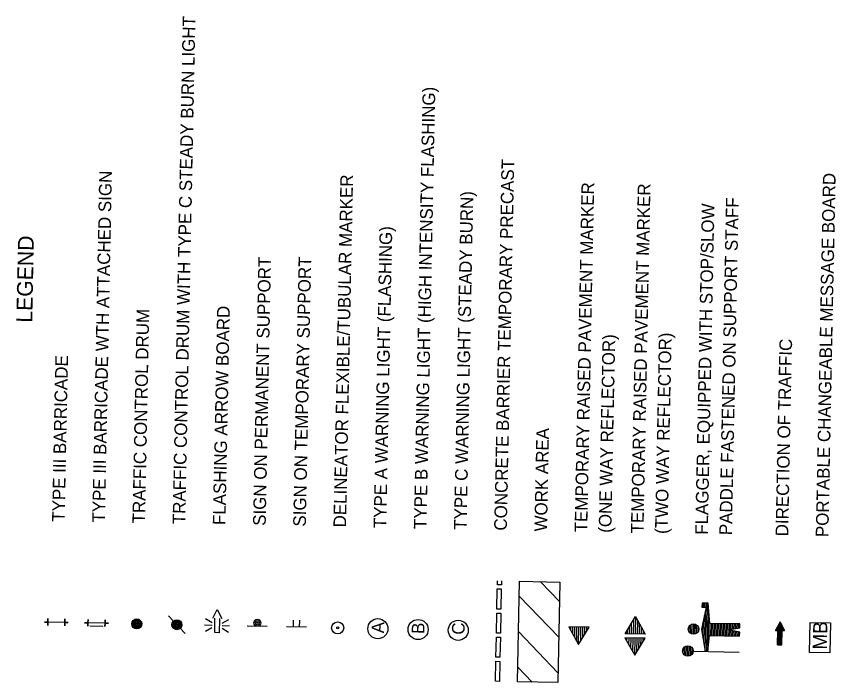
# Model space of a CAD drawing. Extents: x 327762 to 372792, y 127949 to 259367.
# Drawn here: x 327762 to 339988, y 174328 to 184269 of the extents above; entities that cross this region are included whole.
import ezdxf

# ---------------------------------------------------------------- set-up
doc = ezdxf.new("R2010")
doc.units = 0
for name, color, linetype in [('P_TC', 7, 'Continuous'), ('P_TC_BarrierConc', 7, 'Continuous'), ('P_TC_FlowArrow', 7, 'Continuous'), ('P_TC_Text', 7, 'Continuous')]:
    doc.layers.add(name, color=color, linetype=linetype)

msp = doc.modelspace()

# ---------------------------------------------------------------- linework, layer by layer
at = {"layer": 'P_TC'}
for p, q in [((335867, 175537), (335582, 175833)), ((335856, 175006), (335266, 175620)), ((338054, 175453), (337988, 175125)), ((337996, 175515), (337994, 175455)), ((337994, 175455), (338054, 175453)), ((338088, 175513), (337996, 175515)), ((338010, 175454), (338011, 175514)), ((338032, 175454), (338033, 175514)), ((338041, 174793), (338056, 175513)), ((338064, 174793), (338078, 175513)), ((338110, 175212), (338088, 175513)), ((330692, 175289), (330761, 175419)), ((330761, 175419), (330827, 175286)), ((338022, 174936), (338030, 175331)), ((338088, 174884), (338098, 175376)), ((328231, 175231), (328180, 175232)), ((328180, 175232), (328231, 175231)), ((328231, 175231), (328229, 175180)), ((328229, 175180), (328231, 175231)), ((328231, 175231), (328232, 175282)), ((328232, 175282), (328231, 175231)), ((328485, 175226), (328231, 175231)), ((328485, 175226), (328484, 175175)), ((328484, 175175), (328485, 175226)), ((328486, 175277), (328485, 175226)), ((328485, 175226), (328486, 175277)), ((328485, 175226), (328536, 175225)), ((328536, 175225), (328485, 175226)), ((328830, 175219), (328779, 175220)), ((328779, 175220), (328830, 175219)), ((328830, 175219), (328829, 175168)), ((328829, 175168), (328830, 175219)), ((328830, 175219), (328831, 175270)), ((328831, 175270), (328830, 175219)), ((329085, 175214), (328830, 175219)), ((329085, 175214), (329084, 175163)), ((329084, 175163), (329085, 175214)), ((329086, 175265), (329085, 175214)), ((329085, 175214), (329086, 175265)), ((329085, 175214), (329136, 175213)), ((329136, 175213), (329085, 175214)), ((330283, 175062), (330032, 175323)), ((330683, 175219), (330586, 175278)), ((330722, 175074), (330726, 175288)), ((330793, 175286), (330789, 175073)), ((330834, 175216), (330932, 175271)), ((331898, 175157), (331900, 175262)), ((331988, 175156), (331990, 175261)), ((336939, 175212), (336936, 175056)), ((336970, 175263), (336966, 175055)), ((337001, 175314), (336996, 175055)), ((337030, 175262), (337026, 175054)), ((337059, 175209), (337056, 175053)), ((337866, 175049), (337870, 175206)), ((338001, 175049), (338005, 175208)), ((338560, 175203), (338110, 175212)), ((338114, 175032), (338117, 175212)), ((338136, 175032), (338140, 175212)), ((338159, 175031), (338162, 175211)), ((338181, 175031), (338185, 175211)), ((338204, 175030), (338207, 175210)), ((338226, 175030), (338230, 175210)), ((338249, 175029), (338252, 175209)), ((338271, 175029), (338275, 175209)), ((338294, 175029), (338297, 175209)), ((338316, 175028), (338320, 175208)), ((338339, 175028), (338342, 175208)), ((338361, 175027), (338365, 175207)), ((338385, 175119), (338387, 175207)), ((338408, 175122), (338410, 175206)), ((338431, 175125), (338432, 175206)), ((338453, 175128), (338455, 175205)), ((338476, 175131), (338477, 175205)), ((338498, 175135), (338500, 175204)), ((338521, 175138), (338522, 175204)), ((338543, 175141), (338545, 175204)), ((338558, 175143), (338560, 175203)), ((329054, 175164), (328859, 175168)), ((330682, 175182), (330570, 175184)), ((330681, 175144), (330583, 175090)), ((330832, 175141), (330929, 175083)), ((330833, 175179), (330945, 175177)), ((331506, 175165), (331207, 175171)), ((332093, 175153), (331793, 175159)), ((335845, 174476), (335256, 175090)), ((336037, 175109), (336038, 175161)), ((336066, 175056), (336068, 175160)), ((336095, 175004), (336098, 175159)), ((336124, 174951), (336128, 175159)), ((336153, 174898), (336158, 175158)), ((336184, 174950), (336188, 175158)), ((336215, 175001), (336218, 175157)), ((336246, 175052), (336248, 175156)), ((336277, 175104), (336278, 175156)), ((336877, 175109), (336876, 175057)), ((336908, 175160), (336906, 175056)), ((337088, 175157), (337086, 175053)), ((337117, 175104), (337116, 175052)), ((337800, 175088), (337801, 175169)), ((337822, 175064), (337824, 175192)), ((337844, 175052), (337847, 175203)), ((337889, 175052), (337892, 175202)), ((337912, 175062), (337914, 175190)), ((337935, 175086), (337936, 175165)), ((337988, 175125), (338041, 174794)), ((338378, 175117), (338558, 175143)), ((338557, 175083), (338378, 175117)), ((338384, 175027), (338385, 175115)), ((338406, 175026), (338408, 175111)), ((338429, 175026), (338430, 175107)), ((338451, 175025), (338453, 175103)), ((338474, 175025), (338475, 175098)), ((338496, 175024), (338497, 175094)), ((338519, 175024), (338520, 175090)), ((338541, 175024), (338542, 175086)), ((338556, 175023), (338557, 175083)), ((330789, 175073), (330722, 175074)), ((336874, 174945), (336875, 174997)), ((336903, 174893), (336905, 174997)), ((336932, 174840), (336935, 174996)), ((336961, 174787), (336965, 174995)), ((336990, 174735), (336995, 174995)), ((337021, 174786), (337025, 174994)), ((337052, 174838), (337055, 174993)), ((337083, 174889), (337085, 174993)), ((337114, 174940), (337115, 174992)), ((338079, 174793), (338106, 175032)), ((338106, 175032), (338556, 175023)), ((337715, 174760), (337716, 174840)), ((337737, 174735), (337739, 174864)), ((337759, 174724), (337762, 174874)), ((337781, 174720), (337785, 174877)), ((337804, 174723), (337807, 174873)), ((337827, 174734), (337829, 174862)), ((337850, 174758), (337851, 174837)), ((337861, 174797), (338551, 174783)), ((335460, 174335), (335245, 174560))]:
    msp.add_line(p, q, dxfattribs=at)
for points in [[(335241, 174340), (335271, 175840), (335872, 175827), (335842, 174328)], [(337146, 175052), (336846, 175058), (337001, 175314)], [(339601, 174777), (339610, 175227), (339910, 175221), (339901, 174771)], [(336308, 175155), (336008, 175161), (336153, 174898)], [(337145, 174992), (336845, 174998), (336990, 174735)]]:
    msp.add_lwpolyline(points, close=True, dxfattribs=at)
for centre, radius in [((329558, 175204), 75), ((329558, 175204), 60), ((329558, 175204), 45), ((329558, 175204), 30), ((329558, 175204), 15), ((329558, 175204), 7.5), ((330158, 175192), 75), ((330158, 175192), 60), ((330158, 175192), 45), ((330158, 175192), 30), ((330158, 175192), 15), ((331358, 175221), 52.5), ((331358, 175221), 30), ((331358, 175221), 7.5), ((332557, 175144), 90), ((333157, 175132), 150), ((333757, 175120), 150), ((334357, 175108), 150), ((337868, 175127), 78.4), ((330158, 175192), 7.5), ((332557, 175144), 15), ((337783, 174799), 78.4)]:
    msp.add_circle(centre, radius, dxfattribs=at)
at = {"layer": 'P_TC_BarrierConc'}
msp.add_lwpolyline([(335002, 175845), (335001, 175785), (334941, 175786), (334942, 175846)], dxfattribs=at)
for points in [[(334933, 175426), (334939, 175726), (334999, 175725), (334993, 175425)], [(334926, 175066), (334932, 175366), (334992, 175365), (334986, 175065)], [(334919, 174706), (334925, 175006), (334985, 175005), (334979, 174705)], [(334912, 174347), (334918, 174646), (334978, 174645), (334972, 174345)]]:
    msp.add_lwpolyline(points, close=True, dxfattribs=at)
at = {"layer": 'P_TC_FlowArrow'}
for p, q in [((339160, 175236), (339091, 175106)), ((339148, 174891), (339154, 175225)), ((339160, 175236), (339226, 175103)), ((339161, 174891), (339168, 175221)), ((339091, 175106), (339226, 175103)), ((339098, 175106), (339098, 175119)), ((339111, 175106), (339112, 175145)), ((339121, 174891), (339125, 175105)), ((339125, 175106), (339126, 175172)), ((339134, 174891), (339140, 175198)), ((339175, 174890), (339181, 175195)), ((339188, 174890), (339192, 175104)), ((339192, 175104), (339194, 175169)), ((339206, 175104), (339207, 175142)), ((339219, 175104), (339220, 175116)), ((339121, 174891), (339188, 174890)), ((339154, 174891), (339154, 174891))]:
    msp.add_line(p, q, dxfattribs=at)

# ---------------------------------------------------------------- texts
at = {"layer": 'P_TC'}
for s, height, p in [('A', 189, (333250, 175062)), ('B', 189, (333850, 175053)), ('C', 189, (334450, 175041)), ('MB', 210, (339857, 174819))]:
    msp.add_text(s, height=height, rotation=88.8462, dxfattribs=at).set_placement(p)
at = {"layer": 'P_TC_Text'}
for s, height, p in [('TRAFFIC CONTROL DRUM WITH TYPE C STEADY BURN LIGHT', 189, (330282, 176690)), ('TYPE B WARNING LIGHT (HIGH INTENSITY FLASHING)', 189, (333882, 176618)), ('CONCRETE BARRIER TEMPORARY PRECAST', 189, (335081, 176594)), ('TYPE III BARRICADE WTH ATTACHED SIGN', 189, (329083, 176714)), ('DELINEATOR FLEXIBLE/TUBULAR MARKER', 189, (332682, 176642)), ('PORTABLE CHANGEABLE MESSAGE BOARD', 189, (339880, 176497)), ('TEMPORARY RAISED PAVEMENT MARKER', 189, (336281, 176569)), ('TEMPORARY RAISED PAVEMENT MARKER', 189, (337121, 176552)), ('TYPE C WARNING LIGHT (STEADY BURN)', 189, (334481, 176606)), ('FLAGGER, EQUIPPED WITH STOP/SLOW', 189, (338081, 176533)), ('PADDLE FASTENED ON SUPPORT STAFF', 189, (338441, 176526)), ('TYPE A WARNING LIGHT (FLASHING)', 189, (333282, 176630)), ('LEGEND', 236.4, (327998, 179697)), ('SIGN ON PERMANENT SUPPORT', 189, (331482, 176666)), ('SIGN ON TEMPORARY SUPPORT', 189, (332082, 176654)), ('TRAFFIC CONTROL DRUM', 189, (329682, 176702)), ('FLASHING ARROW BOARD', 189, (330882, 176678)), ('(ONE WAY REFLECTOR)', 189, (336641, 176562)), ('(TWO WAY REFLECTOR)', 189, (337481, 176545)), ('DIRECTION OF TRAFFIC', 189, (339280, 176509)), ('TYPE III BARRICADE', 189, (328483, 176726)), ('WORK AREA', 189, (335681, 176581))]:
    msp.add_text(s, height=height, rotation=88.8462, dxfattribs=at).set_placement(p)

doc.saveas('drawing.dxf')
